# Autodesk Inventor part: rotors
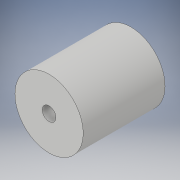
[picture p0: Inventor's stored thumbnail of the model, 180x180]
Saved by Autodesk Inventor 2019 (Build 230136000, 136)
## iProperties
Created: 2021-07
Part Number: rotors
Material: Generic
Document SubType Name: Modeling
Designer: Avinash
Density: 1 g/cm^3
Appearance: Default
Author: Avinash
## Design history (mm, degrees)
sketch "Sketch1"
  geometry: C1 r 25 at (0, 0); 1 further point
  constraints: 1 centre point, 1 coincident
  dimensions: "d0" = 50 diameter of C1
extrude "Extrusion1" new body sketch "Sketch1" distance "d1" = 60; taper "d2" = 0 deg
sketch "Sketch2"
  geometry: C1 r 5 at (0, 0); 1 further point
  constraints: 1 centre point, 1 coincident
  dimensions: "d3" = 10 diameter of C1
extrude "Extrusion2" cut sketch "Sketch2" distance "d4" = 60; taper "d5" = 0 deg
body "Solid1"
